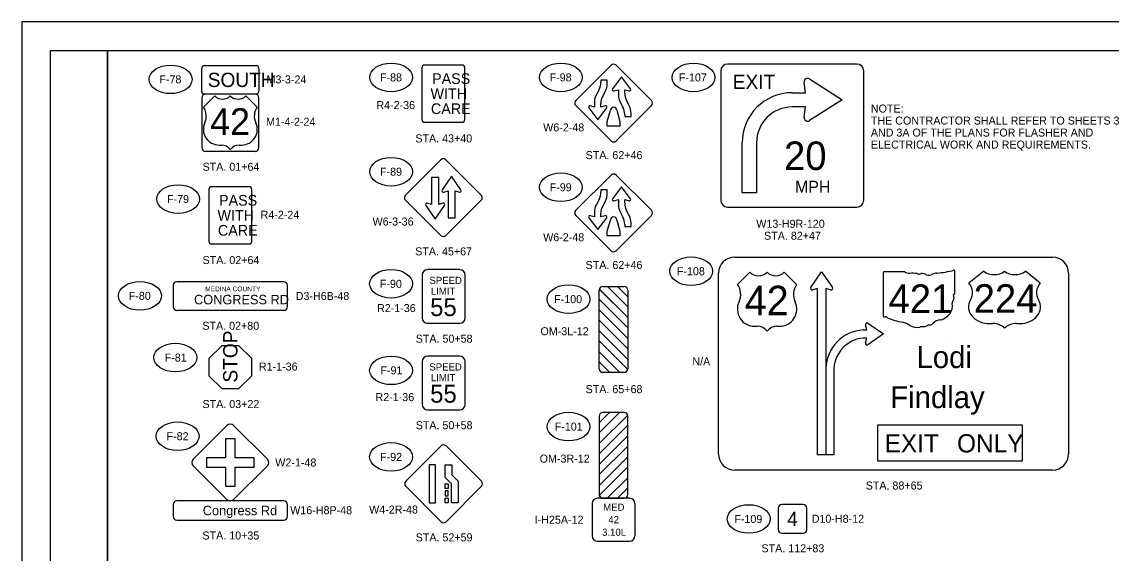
# Model space of a CAD drawing. Extents: x 0 to 34, y 0 to 22.
# Drawn here: x 0 to 19.05, y 12.7 to 22 of the extents above; entities that cross this region are included whole.
import ezdxf

# ---------------------------------------------------------------- set-up
doc = ezdxf.new("R2010")
doc.units = 0
for name, color, linetype in [('SH_Border', 7, 'Continuous'), ('SH_Cut_Line', 7, 'Continuous'), ('SH_Data', 7, 'Continuous'), ('SH_Text', 7, 'Continuous'), ('SN_P_Signs', 7, 'Continuous')]:
    doc.layers.add(name, color=color, linetype=linetype)

msp = doc.modelspace()

# ---------------------------------------------------------------- linework, layer by layer
at = {"layer": 'SH_Border'}
for points in [[(0.5, 21.5), (1.5, 21.5), (1.5, 0.5), (0.5, 0.5)], [(1.5, 21.5), (33.5, 21.5), (33.5, 0.5), (1.5, 0.5)]]:
    msp.add_lwpolyline(points, close=True, dxfattribs=at)
at = {"layer": 'SH_Cut_Line'}
msp.add_lwpolyline([(0, 0), (34, 0), (34, 22), (0, 22)], close=True, dxfattribs=at)
at = {"layer": 'SH_Data'}
msp.add_lwpolyline([(14.967, 14.95), (17.496, 14.95), (17.496, 14.314), (14.967, 14.314)], close=True, dxfattribs=at)
for centre, radius, start, end in [((14.757, 15.912), 0.699, 93.6108, 178.0261), ((14.77, 15.901), 0.57, 95.7978, 181.7619)]:
    msp.add_arc(centre, radius, start, end, dxfattribs=at)
at = {"layer": 'SH_Text'}
for p, q in [((14.058, 15.936), (14.058, 14.425)), ((14.201, 14.425), (13.915, 14.425))]:
    msp.add_line(p, q, dxfattribs=at)
for centre in [(2.602, 20.993), (6.459, 21.027), (9.426, 21.027), (11.746, 21.026), (6.459, 19.377), (9.426, 19.105), (2.734, 18.899), (11.706, 17.637), (6.458, 17.417), (2.066, 17.206), (9.561, 17.148), (2.685, 16.126), (6.458, 15.903), (9.561, 14.919), (2.724, 14.751), (6.458, 14.389), (12.711, 13.303)]:
    msp.add_ellipse(centre, major_axis=(0.375, 0), ratio=0.666667, dxfattribs=at)
at = {"layer": 'SN_P_Signs'}
for p, q in [((3.146, 20.784), (3.146, 21.184)), ((3.196, 21.234), (4.096, 21.234)), ((4.146, 21.184), (4.146, 20.784)), ((14.603, 21.26), (12.343, 21.26)), ((14.603, 21.26), (14.603, 21.26)), ((10.238, 20.98), (10.127, 20.98)), ((10.127, 20.98), (10.127, 20.944)), ((10.238, 20.917), (10.238, 20.98)), ((10.488, 21.035), (10.331, 20.827)), ((10.645, 20.827), (10.488, 21.035)), ((12.223, 21.14), (12.223, 18.88)), ((13.775, 21), (14.348, 20.635)), ((14.723, 18.88), (14.723, 21.14)), ((10.094, 20.814), (10.048, 20.726)), ((10.159, 20.699), (10.206, 20.787)), ((10.355, 20.791), (10.432, 20.812)), ((10.432, 20.812), (10.432, 20.725)), ((10.543, 20.752), (10.543, 20.812)), ((10.543, 20.812), (10.621, 20.791)), ((13.705, 20.76), (13.68, 20.938)), ((3.373, 20.703), (3.178, 20.507)), ((4.096, 20.734), (3.196, 20.734)), ((4.115, 20.507), (3.92, 20.703)), ((10.016, 20.596), (10.016, 20.509)), ((10.465, 20.595), (10.511, 20.507)), ((10.622, 20.534), (10.576, 20.622)), ((13.473, 20.76), (13.705, 20.76)), ((14.348, 20.635), (13.775, 20.271)), ((9.914, 20.494), (10.071, 20.285)), ((9.914, 20.494), (9.914, 20.494)), ((10.016, 20.509), (9.938, 20.529)), ((10.071, 20.285), (10.228, 20.494)), ((10.127, 20.509), (10.127, 20.569)), ((10.204, 20.529), (10.127, 20.509)), ((10.238, 20.258), (10.293, 20.452)), ((10.405, 20.452), (10.46, 20.258)), ((10.655, 20.341), (10.655, 20.404)), ((13.705, 20.51), (13.473, 20.51)), ((13.68, 20.332), (13.705, 20.51)), ((10.238, 20.174), (10.238, 20.258)), ((10.46, 20.258), (10.46, 20.174)), ((10.543, 20.377), (10.543, 20.341)), ((10.543, 20.341), (10.655, 20.341)), ((10.46, 20.174), (10.238, 20.174)), ((3.451, 19.843), (3.49, 19.843)), ((3.803, 19.843), (3.842, 19.843)), ((12.598, 19.01), (12.598, 19.885)), ((12.598, 19.885), (12.598, 19.885)), ((12.848, 19.885), (12.848, 19.01)), ((7.29, 19.278), (7.165, 19.278)), ((7.165, 19.278), (7.165, 18.803)), ((7.29, 18.803), (7.29, 19.278)), ((7.515, 19.298), (7.351, 19.058)), ((7.68, 19.058), (7.515, 19.298)), ((10.238, 19.058), (10.127, 19.058)), ((10.127, 19.058), (10.127, 19.022)), ((10.238, 18.995), (10.238, 19.058)), ((10.488, 19.114), (10.331, 18.905)), ((10.645, 18.905), (10.488, 19.114)), ((7.379, 19.02), (7.453, 19.043)), ((7.453, 19.043), (7.453, 18.569)), ((7.578, 18.569), (7.578, 19.043)), ((7.578, 19.043), (7.652, 19.02)), ((10.094, 18.892), (10.048, 18.804)), ((10.159, 18.777), (10.206, 18.865)), ((10.355, 18.87), (10.432, 18.891)), ((10.432, 18.891), (10.432, 18.803)), ((10.543, 18.831), (10.543, 18.891)), ((10.543, 18.891), (10.621, 18.87)), ((12.848, 19.01), (12.598, 19.01)), ((7.063, 18.788), (7.228, 18.548)), ((7.165, 18.803), (7.091, 18.826)), ((7.228, 18.548), (7.392, 18.788)), ((7.364, 18.826), (7.29, 18.803)), ((10.016, 18.674), (10.016, 18.587)), ((10.465, 18.673), (10.511, 18.585)), ((10.622, 18.613), (10.576, 18.701)), ((12.343, 18.76), (14.603, 18.76)), ((7.453, 18.569), (7.578, 18.569)), ((9.914, 18.573), (10.071, 18.364)), ((9.914, 18.572), (9.914, 18.573)), ((10.016, 18.587), (9.938, 18.608)), ((10.071, 18.364), (10.228, 18.573)), ((10.127, 18.587), (10.127, 18.647)), ((10.204, 18.608), (10.127, 18.587)), ((10.238, 18.336), (10.293, 18.531)), ((10.405, 18.531), (10.46, 18.336)), ((10.655, 18.419), (10.655, 18.483)), ((10.238, 18.253), (10.238, 18.336)), ((10.46, 18.336), (10.46, 18.253)), ((10.543, 18.455), (10.543, 18.419)), ((10.543, 18.419), (10.655, 18.419)), ((10.46, 18.253), (10.238, 18.253)), ((12.731, 17.619), (12.517, 17.404)), ((13.548, 17.404), (13.333, 17.619)), ((15.063, 17.611), (15.063, 16.852)), ((15.441, 17.624), (15.075, 17.624)), ((16.313, 17.246), (16.313, 17.643)), ((16.821, 17.638), (16.56, 17.429)), ((17.81, 17.429), (17.55, 17.638)), ((10.598, 17.013), (10.243, 17.368)), ((10.598, 17.19), (10.419, 17.368)), ((10.598, 16.825), (10.098, 17.325)), ((10.598, 16.648), (10.098, 17.148)), ((16.313, 17.246), (16.313, 17.246)), ((10.598, 16.459), (10.098, 16.959)), ((10.598, 16.282), (10.098, 16.782)), ((10.598, 16.094), (10.098, 16.594)), ((12.817, 16.674), (12.86, 16.674)), ((13.204, 16.674), (13.247, 16.674)), ((16.925, 16.721), (16.977, 16.721)), ((17.394, 16.721), (17.446, 16.721)), ((10.598, 15.917), (10.098, 16.417)), ((16.252, 16.408), (16.252, 16.408)), ((3.496, 16.333), (3.271, 16.108)), ((3.796, 16.333), (3.496, 16.333)), ((4.021, 16.108), (3.796, 16.333)), ((10.457, 15.868), (10.098, 16.228)), ((3.271, 16.108), (3.271, 15.808)), ((4.021, 15.808), (4.021, 16.108)), ((10.281, 15.868), (10.098, 16.051)), ((14.201, 15.883), (14.201, 14.425)), ((3.271, 15.808), (3.496, 15.583)), ((3.796, 15.583), (4.021, 15.808)), ((3.496, 15.583), (3.796, 15.583)), ((10.098, 14.81), (10.453, 15.165)), ((10.098, 14.987), (10.276, 15.165)), ((10.098, 14.621), (10.598, 15.121)), ((10.098, 14.444), (10.598, 14.944)), ((3.73, 14.707), (3.563, 14.707)), ((3.563, 14.707), (3.563, 14.374)), ((3.73, 14.374), (3.73, 14.707)), ((10.098, 14.256), (10.598, 14.756)), ((10.098, 14.079), (10.598, 14.579)), ((3.563, 14.374), (3.23, 14.374)), ((3.23, 14.374), (3.23, 14.207)), ((4.063, 14.374), (3.73, 14.374)), ((4.063, 14.207), (4.063, 14.374)), ((10.098, 13.89), (10.598, 14.39)), ((3.23, 14.207), (3.563, 14.207)), ((3.563, 14.207), (3.563, 13.874)), ((3.73, 13.874), (3.73, 14.207)), ((3.73, 14.207), (4.063, 14.207)), ((7.237, 14.252), (7.124, 14.252)), ((7.124, 14.252), (7.124, 13.585)), ((7.237, 13.585), (7.237, 14.252)), ((7.406, 14.252), (7.518, 14.252)), ((7.406, 14.029), (7.406, 14.252)), ((7.518, 14.252), (7.518, 14.075)), ((10.098, 13.714), (10.598, 14.214)), ((7.516, 13.918), (7.406, 14.029)), ((7.406, 13.835), (7.406, 13.918)), ((7.406, 13.918), (7.456, 13.918)), ((7.456, 13.918), (7.456, 13.835)), ((7.516, 13.585), (7.516, 13.918)), ((7.518, 14.075), (7.629, 13.965)), ((7.629, 13.965), (7.629, 13.585)), ((10.238, 13.665), (10.598, 14.025)), ((3.563, 13.874), (3.73, 13.874)), ((7.456, 13.835), (7.406, 13.835)), ((7.456, 13.793), (7.406, 13.793)), ((7.406, 13.793), (7.406, 13.71)), ((7.456, 13.71), (7.456, 13.793)), ((10.415, 13.665), (10.598, 13.848)), ((7.124, 13.585), (7.237, 13.585)), ((7.406, 13.71), (7.456, 13.71)), ((7.406, 13.585), (7.406, 13.668)), ((7.406, 13.668), (7.456, 13.668)), ((7.456, 13.585), (7.406, 13.585)), ((7.456, 13.668), (7.456, 13.585)), ((7.629, 13.585), (7.516, 13.585))]:
    msp.add_line(p, q, dxfattribs=at)
for points in [[(6.997, 21.195), (6.997, 20.289)], [(7.7, 21.242), (7.043, 21.242)], [(7.747, 20.289), (7.747, 21.195)], [(9.687, 20.624), (10.304, 21.24)], [(10.394, 21.24), (11.011, 20.624)], [(3.146, 20.671), (3.146, 19.796)], [(4.084, 20.734), (3.209, 20.734)], [(4.146, 19.796), (4.146, 20.671)], [(10.304, 19.916), (9.687, 20.533)], [(11.011, 20.533), (10.394, 19.916)], [(7.043, 20.242), (7.7, 20.242)], [(3.209, 19.734), (4.084, 19.734)], [(6.709, 18.968), (7.327, 19.586)], [(7.416, 19.586), (8.034, 18.968)], [(9.687, 18.702), (10.304, 19.319)], [(10.394, 19.319), (11.011, 18.702)], [(3.271, 19.067), (3.271, 18.161)], [(3.975, 19.114), (3.318, 19.114)], [(4.021, 18.161), (4.021, 19.067)], [(7.327, 18.26), (6.709, 18.879)], [(8.034, 18.879), (7.416, 18.26)], [(10.304, 17.995), (9.687, 18.611)], [(11.011, 18.611), (10.394, 17.995)], [(3.318, 18.114), (3.975, 18.114)], [(12.465, 17.884), (18.024, 17.884)], [(7.001, 17.57), (7.001, 16.82)], [(7.658, 17.664), (7.095, 17.664)], [(7.751, 16.82), (7.751, 17.57)], [(12.184, 14.44), (12.184, 17.602)], [(13.798, 17.354), (13.987, 17.628), (14.176, 17.354)], [(18.306, 17.602), (18.306, 14.44)], [(2.646, 17.39), (2.646, 17.015)], [(4.584, 17.453), (2.709, 17.453)], [(4.646, 17.015), (4.646, 17.39)], [(10.16, 17.368), (10.243, 17.368), (10.598, 17.013), (10.598, 16.825), (10.1, 17.322)], [(10.16, 17.368), (10.535, 17.368)], [(10.419, 17.368), (10.535, 17.368)], [(10.598, 17.306), (10.598, 17.19), (10.419, 17.368)], [(13.915, 14.425), (13.915, 17.337), (13.83, 17.31)], [(14.143, 17.31), (14.058, 17.337), (14.058, 15.936)], [(10.098, 15.931), (10.098, 17.306)], [(10.098, 16.959), (10.098, 17.148), (10.598, 16.648), (10.598, 16.459), (10.098, 16.959)], [(10.598, 17.306), (10.598, 15.931)], [(2.709, 16.953), (4.584, 16.953)], [(10.098, 16.594), (10.098, 16.782), (10.598, 16.282), (10.598, 16.094), (10.098, 16.594)], [(7.095, 16.727), (7.658, 16.727)], [(14.713, 16.61), (14.779, 16.61), (14.752, 16.695)], [(14.796, 16.728), (15.07, 16.539), (14.796, 16.35)], [(10.535, 15.868), (10.457, 15.868), (10.098, 16.228), (10.098, 16.417), (10.596, 15.918)], [(14.752, 16.382), (14.779, 16.467), (14.713, 16.467)], [(7.001, 16.056), (7.001, 15.306)], [(7.658, 16.15), (7.095, 16.15)], [(7.751, 15.306), (7.751, 16.056)], [(10.098, 15.931), (10.098, 16.051), (10.281, 15.868)], [(10.535, 15.868), (10.16, 15.868)], [(10.281, 15.868), (10.16, 15.868)], [(7.095, 15.213), (7.658, 15.213)], [(10.098, 15.103), (10.098, 14.987), (10.276, 15.165)], [(10.535, 15.165), (10.453, 15.165), (10.098, 14.81), (10.098, 14.621), (10.595, 15.119)], [(10.098, 15.103), (10.098, 13.728)], [(10.535, 15.165), (10.16, 15.165)], [(10.276, 15.165), (10.16, 15.165)], [(10.598, 13.728), (10.598, 15.103)], [(3.588, 14.938), (2.998, 14.349)], [(4.295, 14.349), (3.705, 14.938)], [(10.598, 14.756), (10.598, 14.944), (10.098, 14.444), (10.098, 14.256), (10.598, 14.756)], [(6.714, 13.963), (7.332, 14.581)], [(7.421, 14.581), (8.039, 13.963)], [(10.598, 14.39), (10.598, 14.579), (10.098, 14.079), (10.098, 13.89), (10.598, 14.39)], [(2.998, 14.231), (3.588, 13.642)], [(3.705, 13.642), (4.295, 14.231)], [(10.16, 13.665), (10.238, 13.665), (10.598, 14.025), (10.598, 14.214), (10.099, 13.715)], [(18.024, 14.158), (12.465, 14.158)], [(7.332, 13.255), (6.714, 13.874)], [(8.039, 13.874), (7.421, 13.255)], [(10.598, 13.728), (10.598, 13.848), (10.415, 13.665)], [(2.646, 13.555), (2.646, 13.347)], [(4.584, 13.618), (2.709, 13.618)], [(4.646, 13.347), (4.646, 13.555)], [(9.973, 13.571), (9.973, 13.009)], [(10.629, 13.665), (10.066, 13.665)], [(10.16, 13.665), (10.535, 13.665)], [(10.415, 13.665), (10.535, 13.665)], [(10.723, 13.009), (10.723, 13.571)], [(13.664, 13.554), (13.289, 13.554)], [(13.226, 13.491), (13.226, 13.116)], [(13.726, 13.116), (13.726, 13.491)], [(2.709, 13.284), (4.584, 13.284)], [(13.289, 13.054), (13.664, 13.054)], [(10.066, 12.915), (10.629, 12.915)]]:
    msp.add_lwpolyline(points, dxfattribs=at)
for centre, radius, start, end in [((3.196, 21.184), 0.05, 90, 180), ((4.096, 21.184), 0.05, 0, 90), ((7.043, 21.195), 0.0469, 90, 180), ((7.7, 21.195), 0.0469, 0, 90), ((10.349, 21.195), 0.064, 45, 135), ((12.343, 21.14), 0.12, 90, 180), ((14.603, 21.14), 0.12, 0, 90), ((13.742, 20.947), 0.0625, 57.5387, 188.1387), ((3.196, 20.784), 0.05, 180, 270), ((4.096, 20.784), 0.05, 270, 0), ((9.849, 20.944), 0.278, 332.1027, 0), ((9.96, 20.917), 0.278, 332.1027, 0), ((10.349, 20.813), 0.0226, 143.0539, 285.0158), ((10.627, 20.813), 0.0226, 254.9842, 36.9461), ((3.209, 20.671), 0.0625, 90, 180), ((3.51, 20.842), 0.195, 225.573, 314.427), ((3.783, 20.842), 0.195, 225.573, 314.427), ((4.084, 20.671), 0.0625, 0, 90), ((9.732, 20.578), 0.064, 135, 225), ((10.293, 20.596), 0.278, 152.1027, 180.0001), ((10.404, 20.569), 0.278, 152.1027, 180), ((10.71, 20.725), 0.278, 179.9999, 207.8973), ((10.821, 20.752), 0.278, 180, 207.8973), ((10.965, 20.578), 0.064, 315, 45), ((13.473, 19.885), 0.875, 90, 180), ((2.954, 20.351), 0.273, 334.5471, 35.0009), ((4.339, 20.351), 0.273, 144.9991, 205.4529), ((9.932, 20.508), 0.0226, 74.9842, 216.9461), ((10.21, 20.508), 0.0226, 323.0539, 105.0158), ((10.349, 20.452), 0.0556, 0, 180), ((10.266, 20.377), 0.278, 0, 27.8973), ((10.377, 20.404), 0.278, 0, 27.8973), ((13.473, 19.885), 0.625, 90, 180), ((3.448, 20.117), 0.273, 154.8319, 270.6383), ((3.845, 20.117), 0.273, 269.3617, 25.1681), ((7.043, 20.289), 0.0469, 180, 270), ((7.7, 20.289), 0.0469, 270, 0), ((13.742, 20.324), 0.0625, 171.8699, 302.4811), ((3.49, 19.648), 0.195, 36.8699, 90), ((3.803, 19.648), 0.195, 90, 143.1301), ((10.349, 19.962), 0.064, 225, 315), ((3.209, 19.796), 0.0625, 180, 270), ((4.084, 19.796), 0.0625, 270, 0), ((7.372, 19.542), 0.0625, 45, 135), ((10.349, 19.273), 0.064, 45, 135), ((3.318, 19.067), 0.0469, 90, 180), ((3.975, 19.067), 0.0469, 0, 90), ((7.372, 19.044), 0.025, 145.5945, 287.3662), ((7.659, 19.044), 0.025, 252.6338, 34.4055), ((6.753, 18.923), 0.0625, 135, 225), ((7.99, 18.923), 0.0625, 315, 45), ((9.849, 19.022), 0.278, 332.1027, 0), ((9.96, 18.995), 0.278, 332.1027, 0), ((10.349, 18.892), 0.0226, 143.0539, 285.0158), ((10.627, 18.892), 0.0226, 254.9842, 36.9461), ((12.343, 18.88), 0.12, 180, 270), ((14.603, 18.88), 0.12, 270, 0), ((7.084, 18.803), 0.025, 72.6338, 214.4055), ((7.372, 18.803), 0.025, 325.5945, 107.3662), ((9.732, 18.657), 0.064, 135, 225), ((10.293, 18.674), 0.278, 152.1027, 180.0001), ((10.404, 18.647), 0.278, 152.1027, 180), ((10.71, 18.803), 0.278, 179.9999, 207.8973), ((10.821, 18.83), 0.278, 180, 207.8973), ((10.965, 18.657), 0.064, 315, 45), ((9.932, 18.586), 0.0226, 74.9842, 216.9461), ((10.21, 18.586), 0.0226, 323.0539, 105.0158), ((10.349, 18.53), 0.0556, 0, 180), ((10.266, 18.455), 0.278, 0, 27.8973), ((10.377, 18.483), 0.278, 0, 27.8973), ((3.318, 18.161), 0.0469, 180, 270), ((3.975, 18.161), 0.0469, 270, 0), ((7.372, 18.305), 0.0625, 225, 315), ((10.349, 18.04), 0.064, 225, 315), ((12.465, 17.602), 0.281, 90, 180), ((18.024, 17.602), 0.281, 0, 90), ((7.095, 17.57), 0.0938, 90, 180), ((7.658, 17.57), 0.0938, 0, 90), ((12.882, 17.773), 0.215, 225.573, 314.427), ((13.183, 17.773), 0.215, 225.573, 314.427), ((2.709, 17.39), 0.0625, 90, 180), ((4.584, 17.39), 0.0625, 0, 90), ((10.16, 17.306), 0.0625, 90, 180), ((10.16, 17.306), 0.0625, 90, 164.7237), ((10.535, 17.306), 0.0625, 0, 90), ((10.535, 17.306), 0.0625, 0, 90), ((12.27, 17.232), 0.301, 334.5471, 35.0009), ((13.794, 17.232), 0.301, 144.9991, 205.4529), ((13.822, 17.338), 0.029, 145.3614, 287.7282), ((14.152, 17.338), 0.029, 252.2718, 34.6386), ((2.709, 17.015), 0.0625, 180, 270), ((4.584, 17.015), 0.0625, 270, 0), ((12.814, 16.975), 0.301, 154.8319, 270.6383), ((13.25, 16.975), 0.301, 269.3617, 25.1681), ((7.095, 16.82), 0.0938, 180, 270), ((7.658, 16.82), 0.0938, 270, 0), ((12.86, 16.459), 0.215, 36.8699, 90), ((13.204, 16.459), 0.215, 90, 143.1301), ((14.78, 16.704), 0.029, 55.3614, 197.7282), ((14.78, 16.373), 0.029, 162.2718, 304.6386), ((7.095, 16.056), 0.0938, 90, 180), ((7.658, 16.056), 0.0938, 0, 90), ((10.16, 15.931), 0.0625, 180, 270), ((10.16, 15.931), 0.0625, 180, 270), ((10.535, 15.931), 0.0625, 270, 360), ((10.535, 15.931), 0.0625, 270, 348.268), ((7.095, 15.306), 0.0938, 180, 270), ((7.658, 15.306), 0.0938, 270, 0), ((10.16, 15.103), 0.0625, 90, 180), ((10.16, 15.103), 0.0625, 90, 180), ((10.535, 15.103), 0.0625, 0, 90), ((10.535, 15.103), 0.0625, 15.2763, 90), ((3.646, 14.88), 0.0833, 45, 135), ((7.376, 14.537), 0.0625, 45, 135), ((3.057, 14.29), 0.0833, 135, 225), ((4.236, 14.29), 0.0833, 315, 45), ((12.465, 14.44), 0.281, 180, 270), ((18.024, 14.44), 0.281, 270, 0), ((6.758, 13.918), 0.0625, 135, 225), ((7.995, 13.918), 0.0625, 315, 45), ((10.16, 13.728), 0.0625, 180, 270), ((10.535, 13.728), 0.0625, 270, 0), ((10.535, 13.728), 0.0625, 270, 0), ((2.709, 13.555), 0.0625, 90, 180), ((3.646, 13.701), 0.0833, 225, 315), ((4.584, 13.555), 0.0625, 0, 90), ((10.066, 13.571), 0.0938, 90, 180), ((10.16, 13.728), 0.0625, 191.732, 270), ((10.629, 13.571), 0.0938, 0, 90), ((13.289, 13.491), 0.0625, 90, 180), ((13.664, 13.491), 0.0625, 0, 90), ((2.709, 13.347), 0.0625, 180, 270), ((4.584, 13.347), 0.0625, 270, 0), ((7.376, 13.3), 0.0625, 225, 315), ((10.066, 13.009), 0.0938, 180, 270), ((10.629, 13.009), 0.0938, 270, 0), ((13.289, 13.116), 0.0625, 180, 270), ((13.664, 13.116), 0.0625, 270, 0)]:
    msp.add_arc(centre, radius, start, end, dxfattribs=at)
for centre, major_axis, start_param, end_param in [((15.077, 17.613), (0.0145, 0), 1.712693, 3.28349), ((15.528, 17.712), (0.14, 0), 4.042523, 4.731795), ((15.575, 17.198), (0.504, 0), 1.404758, 1.657858), ((15.69, 17.617), (0.0405, 0), 3.836095, 5.185415), ((15.749, 17.529), (0.0842, 0), 0.950623, 2.079405), ((15.858, 17.649), (0.101, 0), 4.081561, 5.145723), ((16.037, 17.392), (0.267, 0), 1.699011, 2.107814), ((15.868, 18.659), (1.326, 0), 4.814394, 5.042369), ((16.299, 17.645), (0.0139, 0), 6.141152, 7.989035), ((17.003, 17.786), (-0.26, 0), 0.795399, 2.346194), ((17.368, 17.786), (-0.26, 0), 0.795399, 2.346194), ((16.262, 17.262), (0.365, 0), 5.838949, 6.894067), ((18.109, 17.262), (-0.365, 0), 5.672304, 6.727422), ((16.31, 17.217), (0.0215, 0), 1.883978, 3.671073), ((16.173, 17.167), (0.129, 0), 5.934695, 6.695948), ((16.298, 17.244), (0.0149, 0), 5.05454, 6.418171), ((15.942, 17.029), (0.332, 0), 5.101752, 6.440018), ((16.363, 17.08), (0.0941, 0), 2.387724, 3.262537), ((16.921, 17.013), (0.365, 0), 2.702327, 4.723529), ((17.45, 17.013), (-0.365, 0), 1.559657, 3.580859), ((15.077, 16.85), (0.0146, 0), 3.00124, 4.508301), ((15.08, 16.928), (0.111, 0), 4.665946, 4.897461), ((15.102, 16.808), (0.0402, 0), 0.519207, 1.627899), ((15.61, 17.49), (0.957, 0), 4.195997, 4.488961), ((16.082, 16.639), (0.182, 0), 1.647645, 2.488434), ((15.325, 16.511), (0.3, 0), 0.823519, 1.323587), ((15.649, 16.805), (0.19, 0), 4.026481, 4.996735), ((15.758, 16.542), (0.156, 0), 1.495662, 1.94098), ((15.772, 16.748), (0.101, 0), 4.691044, 5.507374), ((15.864, 16.674), (0.0285, 0), 1.147584, 2.315152), ((15.852, 16.779), (0.107, 0), 4.937069, 5.64225), ((16.977, 16.513), (-0.26, 0), 3.785094, 4.712389), ((17.394, 16.513), (-0.26, 0), 4.712389, 5.639684)]:
    msp.add_ellipse(centre, major_axis=major_axis, ratio=0.8, start_param=start_param, end_param=end_param, dxfattribs=at)

# ---------------------------------------------------------------- texts
at = {"layer": 'SH_Text'}
for s, p in [('F-78', (2.406, 20.923)), ('M3-3-24', (4.279, 20.922)), ('F-88', (6.264, 20.957)), ('F-98', (9.23, 20.957)), ('F-107', (11.49, 20.956)), ('R4-2-36', (6.2, 20.473)), ('NOTE:', (14.847, 20.412)), ('M1-4-2-24', (4.271, 20.182)), ('W6-2-48', (9.117, 20.082)), ('THE CONTRACTOR SHALL REFER TO SHEETS 3', (14.847, 20.202)), ('STA. 43+40', (6.882, 19.89)), ('AND 3A OF THE PLANS FOR FLASHER AND', (14.847, 19.992)), ('ELECTRICAL WORK AND REQUIREMENTS.', (14.847, 19.782)), ('STA. 62+46', (9.859, 19.598)), ('STA. 01+64', (3.161, 19.394)), ('F-89', (6.264, 19.307)), ('F-99', (9.231, 19.035)), ('F-79', (2.539, 18.829)), ('R4-2-24', (4.176, 18.554)), ('W6-3-36', (6.133, 18.436)), ('W13-H9R-120', (12.844, 18.397)), ('W6-2-48', (9.117, 18.161)), ('STA. 82+47', (12.98, 18.187)), ('STA. 45+67', (6.879, 17.914)), ('STA. 02+64', (3.161, 17.762)), ('STA. 62+46', (9.859, 17.676)), ('F-108', (11.455, 17.567)), ('F-90', (6.262, 17.347)), ('F-80', (1.87, 17.136)), ('D3-H6B-48', (4.79, 17.133)), ('F-100', (9.309, 17.078)), ('R2-1-36', (6.212, 16.922)), ('STA. 02+80', (3.157, 16.613)), ('OM-3L-12', (9.07, 16.517)), ('STA. 50+58', (6.888, 16.387)), ('F-81', (2.499, 16.056)), ('R1-1-36', (4.146, 15.899)), ('N/A', (11.726, 15.988)), ('F-91', (6.271, 15.833)), ('STA. 65+68', (9.859, 15.504)), ('R2-1-36', (6.185, 15.365)), ('STA. 03+22', (3.16, 15.243)), ('STA. 50+58', (6.888, 14.873)), ('F-101', (9.319, 14.849)), ('F-82', (2.532, 14.681)), ('W2-1-48', (4.433, 14.221)), ('F-92', (6.265, 14.319)), ('OM-3R-12', (9.056, 14.289)), ('STA. 88+65', (14.757, 13.818)), ('W16-H8P-48', (4.694, 13.386)), ('W4-2R-48', (6.074, 13.398)), ('I-H25A-12', (8.969, 13.22)), ('F-109', (12.46, 13.233)), ('D10-H8-12', (13.813, 13.237)), ('STA. 10+35', (3.159, 12.944)), ('STA. 52+59', (6.888, 12.911)), ('STA. 112+83', (12.935, 12.72))]:
    msp.add_text(s, height=0.14, dxfattribs=at).set_placement(p)
at = {"layer": 'SN_P_Signs'}
for s, height, p in [('SOUTH', 0.25, (3.251, 20.859)), ('PASS', 0.1869, (7.175, 20.912)), ('EXIT', 0.25, (12.432, 20.823)), ('WITH', 0.1869, (7.147, 20.649)), ('CARE', 0.1869, (7.155, 20.386)), ('42', 0.4688, (3.293, 20.019)), ('20', 0.5, (13.329, 19.406)), ('MPH', 0.2083, (13.521, 19.01)), ('PASS', 0.1869, (3.45, 18.784)), ('WITH', 0.1869, (3.422, 18.521)), ('CARE', 0.1869, (3.43, 18.259)), ('SPEED', 0.125, (7.128, 17.414)), ('MEDINA COUNTY', 0.08333, (3.207, 17.286)), ('LIMIT', 0.125, (7.154, 17.227)), ('42', 0.5156, (12.643, 16.867)), ('421', 0.5, (15.157, 16.906)), ('224', 0.5, (16.645, 16.909)), ('CONGRESS RD', 0.16667, (3.012, 17.057)), ('55', 0.3125, (7.141, 16.852)), ('Lodi', 0.3828, (15.646, 15.943)), ('SPEED', 0.125, (7.128, 15.9)), ('LIMIT', 0.125, (7.154, 15.713)), ('55', 0.3125, (7.141, 15.338)), ('Findlay', 0.3828, (15.187, 15.242)), ('EXIT', 0.319, (15.088, 14.467)), ('ONLY', 0.319, (16.354, 14.467)), ('Congress Rd', 0.16665, (3.165, 13.368)), ('MED', 0.125, (10.167, 13.446)), ('42', 0.125, (10.257, 13.228)), ('4', 0.25, (13.384, 13.179)), ('3.10L', 0.125, (10.148, 13.009))]:
    msp.add_text(s, height=height, dxfattribs=at).set_placement(p)
msp.add_text('STOP', height=0.25, rotation=90, dxfattribs=at).set_placement((3.771, 15.689))

doc.saveas('drawing.dxf')
